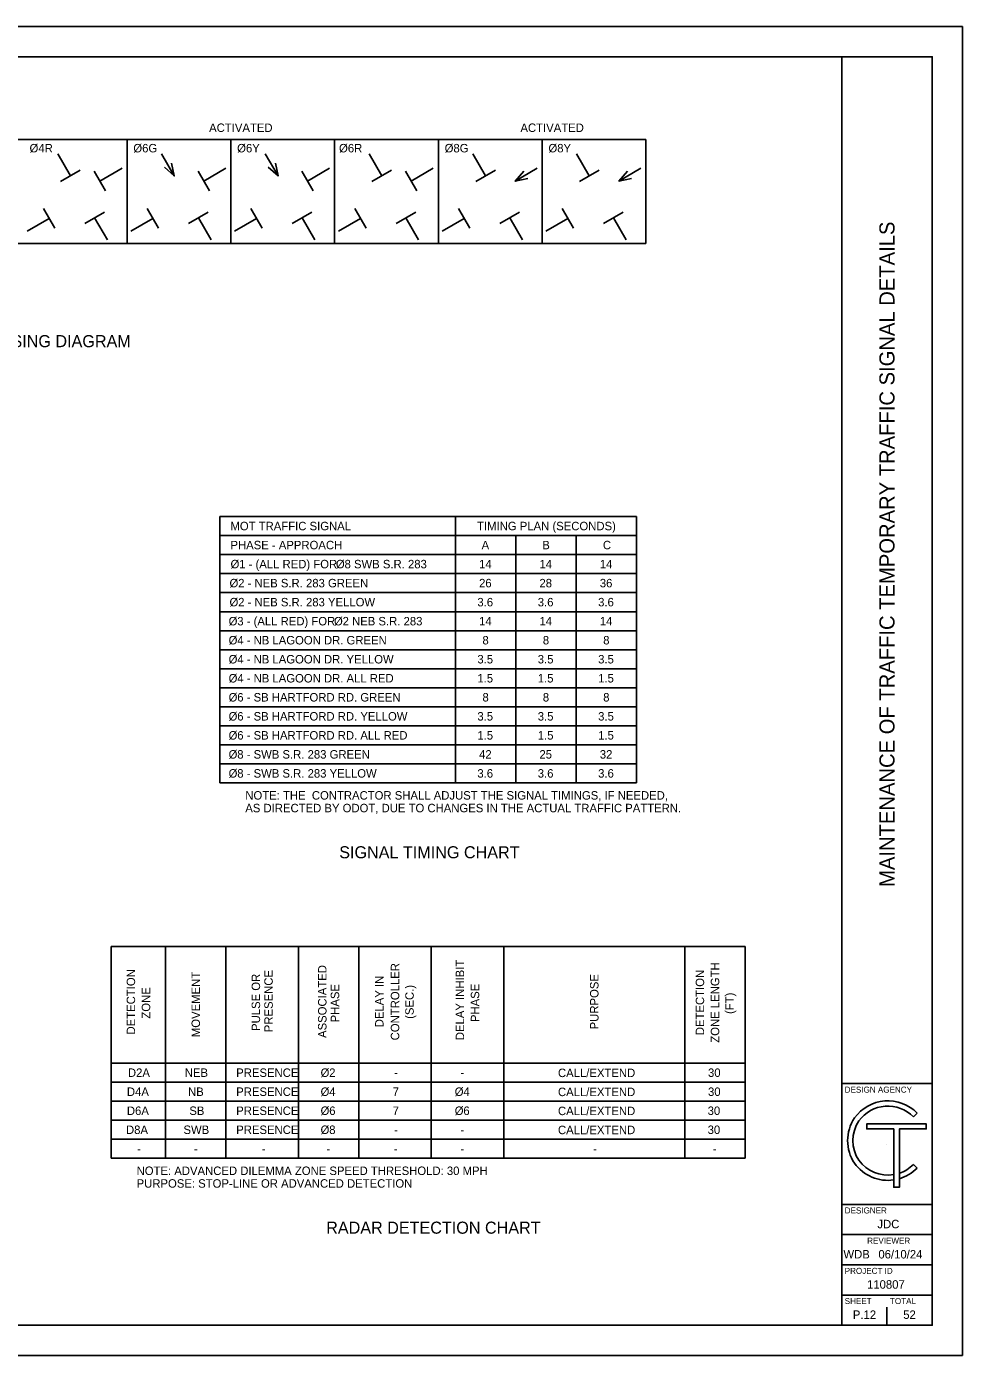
# Model space of a CAD drawing. Extents: x 0 to 34, y 0 to 22.
# Drawn here: x 18.5 to 34, y 0 to 22 of the extents above; entities that cross this region are included whole.
import ezdxf

# ---------------------------------------------------------------- set-up
doc = ezdxf.new("R2010")
doc.units = 0
for name, color, linetype in [('Default', 7, 'Continuous'), ('SG_P_Text', 7, 'Continuous'), ('SH_Border', 7, 'Continuous'), ('SH_Cut_Line', 7, 'Continuous'), ('SH_Data', 7, 'Continuous'), ('SH_Text', 7, 'Continuous'), ('ST_Details', 7, 'Continuous'), ('ST_Text', 7, 'Continuous')]:
    doc.layers.add(name, color=color, linetype=linetype)

msp = doc.modelspace()

# ---------------------------------------------------------------- linework, layer by layer
at = {"layer": 'Default'}
msp.add_line((22.402, 4.681), (22.402, 4.681), dxfattribs=at)
at = {"layer": 'SH_Border'}
for p, q in [((32, 0.5), (32, 21.5)), ((21.702, 9.478), (21.702, 13.888)), ((21.702, 13.888), (28.602, 13.888)), ((25.602, 9.478), (25.602, 13.888)), ((28.602, 9.478), (28.602, 13.888)), ((21.702, 13.573), (28.602, 13.573)), ((26.602, 9.478), (26.602, 13.573)), ((27.602, 9.478), (27.602, 13.573)), ((21.702, 13.258), (28.602, 13.258)), ((28.602, 12.943), (21.702, 12.943)), ((28.602, 12.628), (21.702, 12.628)), ((28.602, 12.313), (21.702, 12.313)), ((28.602, 11.998), (21.702, 11.998)), ((28.602, 11.683), (21.702, 11.683)), ((28.602, 11.368), (21.702, 11.368)), ((28.602, 11.053), (21.702, 11.053)), ((28.602, 10.738), (21.702, 10.738)), ((28.602, 10.423), (21.702, 10.423)), ((28.602, 10.108), (21.702, 10.108)), ((28.602, 9.793), (21.702, 9.793)), ((28.602, 9.478), (21.702, 9.478)), ((19.902, 3.263), (19.902, 6.77)), ((19.902, 6.77), (30.402, 6.77)), ((20.802, 3.263), (20.802, 6.77)), ((21.802, 3.263), (21.802, 6.77)), ((23.002, 3.263), (23.002, 6.77)), ((24.002, 3.263), (24.002, 6.77)), ((25.202, 6.77), (25.202, 3.263)), ((26.402, 6.77), (26.402, 3.263)), ((26.402, 6.77), (26.402, 3.263)), ((29.402, 6.77), (29.402, 3.263)), ((30.402, 6.77), (30.402, 3.263)), ((19.902, 4.838), (30.402, 4.838)), ((30.402, 4.523), (19.902, 4.523)), ((32, 4.5), (33.5, 4.5)), ((30.402, 4.208), (19.902, 4.208)), ((30.402, 3.893), (19.902, 3.893)), ((30.402, 3.578), (19.902, 3.578)), ((30.402, 3.263), (19.902, 3.263)), ((32, 2.5), (33.5, 2.5)), ((32, 2), (33.5, 2)), ((32, 1.5), (33.5, 1.5)), ((32, 1), (33.5, 1))]:
    msp.add_line(p, q, dxfattribs=at)
msp.add_lwpolyline([(1.5, 21.5), (33.5, 21.5), (33.5, 0.5), (1.5, 0.5)], close=True, dxfattribs=at)
at = {"layer": 'SH_Cut_Line'}
msp.add_lwpolyline([(0, 0), (34, 0), (34, 22), (0, 22)], close=True, dxfattribs=at)
at = {"layer": 'SH_Data'}
for p, q in [((32.75, 3.5), (32.75, 3.5)), ((32.375, 0.675), (32.375, 0.675)), ((32.75, 0.5), (32.75, 0.8))]:
    msp.add_line(p, q, dxfattribs=at)
at = {"layer": 'SH_Text'}
for p, q in [((33.249, 4.013), (33.187, 3.952)), ((33.249, 4.013), (33.187, 3.952)), ((33.402, 3.833), (32.414, 3.833)), ((32.414, 3.833), (32.414, 3.751)), ((32.414, 3.751), (32.863, 3.751)), ((32.863, 3.751), (32.863, 2.785)), ((32.956, 2.785), (32.956, 3.751)), ((32.956, 3.751), (33.402, 3.751)), ((33.402, 3.751), (33.402, 3.833)), ((33.187, 3.16), (33.249, 3.099)), ((33.187, 3.16), (33.249, 3.099)), ((32.863, 2.993), (32.863, 2.905)), ((32.863, 2.993), (32.863, 2.905)), ((32.956, 2.925), (32.956, 3.016)), ((32.956, 2.925), (32.956, 3.016)), ((32.863, 2.785), (32.956, 2.785))]:
    msp.add_line(p, q, dxfattribs=at)
for points in [[(20.902, 19.738), (20.945, 19.527), (20.784, 19.67)], [(22.62, 19.738), (22.664, 19.527), (22.502, 19.67)], [(26.801, 19.486), (26.59, 19.443), (26.733, 19.604)], [(28.52, 19.486), (28.309, 19.443), (28.452, 19.604)]]:
    msp.add_lwpolyline(points, dxfattribs=at)
msp.add_lwpolyline([(32.863, 3.751), (32.863, 2.785), (32.956, 2.785), (32.956, 3.751), (33.402, 3.751), (33.402, 3.833), (32.414, 3.833), (32.414, 3.751)], close=True, dxfattribs=at)
for centre, radius, start, end in [((32.766, 3.535), 0.68, 44.7027, 144.3276), ((32.766, 3.535), 0.68, 44.7027, 144.3276), ((32.766, 3.535), 0.593, 44.7362, 144.1102), ((32.766, 3.535), 0.593, 44.7362, 144.1102), ((32.764, 3.556), 0.666, 145.7329, 214.2671), ((32.764, 3.556), 0.666, 145.7329, 214.2671), ((32.764, 3.556), 0.579, 145.7266, 214.2734), ((32.764, 3.556), 0.579, 145.7266, 214.2734), ((32.766, 3.578), 0.68, 215.6724, 278.2613), ((32.766, 3.578), 0.68, 215.6724, 278.2613), ((32.766, 3.578), 0.593, 215.8898, 279.4882), ((32.766, 3.578), 0.593, 215.8898, 279.4882), ((32.766, 3.578), 0.593, 288.6992, 315.2638), ((32.766, 3.578), 0.593, 288.6992, 315.2638), ((32.766, 3.578), 0.68, 286.2291, 315.2973), ((32.766, 3.578), 0.68, 286.2291, 315.2973)]:
    msp.add_arc(centre, radius, start, end, dxfattribs=at)
at = {"layer": 'ST_Details'}
for p, q in [((4.697, 20.13), (28.758, 20.13)), ((20.165, 20.13), (20.165, 18.411)), ((21.883, 20.13), (21.883, 18.411)), ((23.602, 20.13), (23.602, 18.411)), ((25.321, 20.13), (25.321, 18.411)), ((27.039, 20.13), (27.039, 18.411)), ((28.758, 20.13), (28.758, 18.411)), ((19.226, 19.527), (19.016, 19.892)), ((20.945, 19.527), (20.734, 19.892)), ((22.664, 19.527), (22.453, 19.892)), ((24.382, 19.527), (24.172, 19.892)), ((26.101, 19.527), (25.89, 19.892)), ((27.82, 19.527), (27.609, 19.892)), ((19.063, 19.433), (19.389, 19.621)), ((19.621, 19.606), (19.809, 19.28)), ((19.715, 19.443), (20.08, 19.654)), ((21.34, 19.606), (21.528, 19.28)), ((21.434, 19.443), (21.799, 19.654)), ((23.059, 19.606), (23.247, 19.28)), ((23.153, 19.443), (23.518, 19.654)), ((24.219, 19.433), (24.545, 19.621)), ((24.777, 19.606), (24.965, 19.28)), ((24.871, 19.443), (25.236, 19.654)), ((25.938, 19.433), (26.264, 19.621)), ((26.59, 19.443), (26.955, 19.654)), ((27.657, 19.433), (27.983, 19.621)), ((28.309, 19.443), (28.674, 19.654)), ((18.967, 18.66), (18.779, 18.986)), ((19.789, 18.929), (19.463, 18.741)), ((20.686, 18.66), (20.498, 18.986)), ((21.508, 18.929), (21.182, 18.741)), ((22.404, 18.66), (22.216, 18.986)), ((23.226, 18.929), (22.901, 18.741)), ((24.123, 18.66), (23.935, 18.986)), ((24.945, 18.929), (24.619, 18.741)), ((25.842, 18.66), (25.654, 18.986)), ((26.664, 18.929), (26.338, 18.741)), ((27.56, 18.66), (27.372, 18.986)), ((28.383, 18.929), (28.057, 18.741)), ((18.873, 18.823), (18.508, 18.612)), ((19.626, 18.835), (19.837, 18.47)), ((20.592, 18.823), (20.227, 18.612)), ((21.345, 18.835), (21.556, 18.47)), ((22.31, 18.823), (21.945, 18.612)), ((23.063, 18.835), (23.274, 18.47)), ((24.029, 18.823), (23.664, 18.612)), ((24.782, 18.835), (24.993, 18.47)), ((25.748, 18.823), (25.383, 18.612)), ((26.501, 18.835), (26.712, 18.47)), ((27.466, 18.823), (27.101, 18.612)), ((28.22, 18.835), (28.43, 18.47)), ((4.697, 18.411), (28.758, 18.411))]:
    msp.add_line(p, q, dxfattribs=at)

# ---------------------------------------------------------------- texts
at = {"layer": 'SG_P_Text'}
for s, p in [('NOTE: THE  CONTRACTOR SHALL ADJUST THE SIGNAL TIMINGS, IF NEEDED, ', (22.122, 9.202)), ('AS DIRECTED BY ODOT, DUE TO CHANGES IN THE ACTUAL TRAFFIC PATTERN.', (22.122, 8.992)), ('NOTE: ADVANCED DILEMMA ZONE SPEED THRESHOLD: 30 MPH', (20.322, 2.987)), ('PURPOSE: STOP-LINE OR ADVANCED DETECTION', (20.322, 2.777))]:
    msp.add_text(s, height=0.14, rotation=0, dxfattribs=at).set_placement(p)
at = {"layer": 'SH_Data'}
msp.add_text('MAINTENANCE OF TRAFFIC TEMPORARY TRAFFIC SIGNAL DETAILS', height=0.25, rotation=90, dxfattribs=at).set_placement((32.875, 7.757))
for s, height, p in [('DESIGN AGENCY', 0.1, (32.05, 4.35)), ('DESIGNER', 0.1, (32.05, 2.35)), ('JDC', 0.14, (32.591, 2.105)), ('REVIEWER', 0.1, (32.422, 1.85)), ('WDB', 0.14, (32.029, 1.605)), ('06/10/24', 0.14, (32.608, 1.605)), ('PROJECT ID', 0.1, (32.05, 1.35)), ('110807', 0.14, (32.42, 1.105)), ('SHEET', 0.1, (32.05, 0.85)), ('TOTAL', 0.1, (32.8, 0.85)), ('P.12', 0.14, (32.185, 0.605)), ('52', 0.14, (33.019, 0.605))]:
    msp.add_text(s, height=height, dxfattribs=at).set_placement(p)
at = {"layer": 'SH_Text'}
for s, p in [('TEMPORARY TRAFFIC SIGNAL PHASING DIAGRAM', (13.672, 16.692)), ('SIGNAL TIMING CHART', (23.678, 8.23)), ('RADAR DETECTION CHART', (23.462, 2.015))]:
    msp.add_text(s, height=0.2, dxfattribs=at).set_placement(p)
for s, rotation, p in [('MOT TRAFFIC SIGNAL', 359.9999, (21.876, 13.661)), ('TIMING PLAN (SECONDS)', 359.9999, (25.961, 13.661)), ('PHASE - APPROACH', 359.9999, (21.876, 13.346)), ('A', 359.9999, (26.036, 13.346)), ('B', 359.9999, (27.041, 13.346)), ('C', 359.9999, (28.045, 13.346)), ('Ø', 359.9999, (21.878, 13.031)), ('1 - (ALL RED) FOR ', 359.9999, (22.021, 13.031)), ('Ø', 359.9999, (23.623, 13.031)), ('8 SWB S.R. 283', 359.9999, (23.766, 13.031)), ('14', 359.9999, (25.994, 13.031)), ('14', 359.9999, (26.994, 13.031)), ('14', 359.9999, (27.994, 13.031)), ('Ø', 359.9999, (21.861, 12.716)), ('2 - NEB S.R. 283 GREEN', 359.9999, (22.004, 12.716)), ('26', 359.9999, (25.994, 12.716)), ('28', 359.9999, (26.994, 12.716)), ('36', 359.9999, (27.994, 12.716)), ('Ø', 359.9999, (21.861, 12.401)), ('2 - NEB S.R. 283 YELLOW', 359.9999, (22.004, 12.401)), ('3.6', 359.9999, (25.966, 12.401)), ('3.6', 359.9999, (26.966, 12.401)), ('3.6', 359.9999, (27.966, 12.401)), ('Ø', 359.9999, (21.846, 12.086)), ('3 - (ALL RED) FOR ', 359.9999, (21.989, 12.086)), ('Ø', 359.9999, (23.591, 12.086)), ('2 NEB S.R. 283', 359.9999, (23.734, 12.086)), ('14', 359.9999, (25.994, 12.086)), ('14', 359.9999, (26.994, 12.086)), ('14', 359.9999, (27.994, 12.086)), ('Ø', 359.9999, (21.846, 11.771)), ('4 - NB LAGOON DR. GREEN', 359.9999, (21.989, 11.771)), ('8', 359.9999, (26.05, 11.771)), ('8', 359.9999, (27.05, 11.771)), ('8', 359.9999, (28.05, 11.771)), ('Ø', 359.9999, (21.846, 11.456)), ('4 - NB LAGOON DR. YELLOW', 359.9999, (21.989, 11.456)), ('3.5', 359.9999, (25.966, 11.456)), ('3.5', 359.9999, (26.966, 11.456)), ('3.5', 359.9999, (27.966, 11.456)), ('Ø', 359.9999, (21.846, 11.141)), ('4 - NB LAGOON DR. ALL RED', 359.9999, (21.989, 11.141)), ('1.5', 359.9999, (25.966, 11.141)), ('1.5', 359.9999, (26.966, 11.141)), ('1.5', 359.9999, (27.966, 11.141)), ('Ø', 359.9999, (21.846, 10.826)), ('6 - SB HARTFORD RD. GREEN', 359.9999, (21.989, 10.826)), ('8', 359.9999, (26.05, 10.826)), ('8', 359.9999, (27.05, 10.826)), ('8', 359.9999, (28.05, 10.826)), ('Ø', 359.9999, (21.846, 10.511)), ('6 - SB HARTFORD RD. YELLOW', 359.9999, (21.989, 10.511)), ('3.5', 359.9999, (25.966, 10.511)), ('3.5', 359.9999, (26.966, 10.511)), ('3.5', 359.9999, (27.966, 10.511)), ('Ø', 359.9999, (21.846, 10.196)), ('6 - SB HARTFORD RD. ALL RED', 359.9999, (21.989, 10.196)), ('1.5', 359.9999, (25.966, 10.196)), ('1.5', 359.9999, (26.966, 10.196)), ('1.5', 359.9999, (27.966, 10.196)), ('Ø', 359.9999, (21.846, 9.881)), ('8 - SWB S.R. 283 GREEN', 359.9999, (21.989, 9.881)), ('42', 359.9999, (25.994, 9.881)), ('25', 359.9999, (26.994, 9.881)), ('32', 359.9999, (27.994, 9.881)), ('Ø', 359.9999, (21.846, 9.566)), ('8 - SWB S.R. 283 YELLOW', 359.9999, (21.989, 9.566)), ('3.6', 359.9999, (25.966, 9.566)), ('3.6', 359.9999, (26.966, 9.566)), ('3.6', 359.9999, (27.966, 9.566)), ('ASSOCIATED', 89.9999, (23.467, 5.256)), ('CONTROLLER', 89.9999, (24.672, 5.216)), ('DELAY INHIBIT', 89.9999, (25.747, 5.219)), ('ZONE LENGTH', 89.9999, (29.972, 5.177)), ('DETECTION', 89.9999, (20.297, 5.313)), ('MOVEMENT', 89.9999, (21.372, 5.269)), ('PULSE OR', 89.9999, (22.367, 5.372)), ('PRESENCE', 89.9999, (22.577, 5.351)), ('DELAY IN', 89.9999, (24.412, 5.433)), ('PURPOSE', 89.9999, (27.972, 5.398)), ('DETECTION', 89.9999, (29.722, 5.302)), ('ZONE', 89.9999, (20.547, 5.576)), ('PHASE', 89.9999, (23.677, 5.514)), ('(SEC.)', 89.9999, (24.912, 5.572)), ('PHASE', 89.9999, (25.997, 5.519)), ('(FT)', 89.9999, (30.212, 5.653)), ('D2A', 359.9999, (20.178, 4.611)), ('NEB', 359.9999, (21.12, 4.611)), ('PRESENCE', 0, (21.972, 4.611)), ('Ø', 0, (23.369, 4.611)), ('2', 0, (23.512, 4.611)), ('-', 0, (24.585, 4.611)), ('-', 0, (25.685, 4.611)), ('CALL/EXTEND', 0, (27.301, 4.608)), ('30', 0, (29.786, 4.611)), ('D4A', 359.9999, (20.161, 4.296)), ('NB', 359.9999, (21.174, 4.296)), ('PRESENCE', 0, (21.972, 4.296)), ('Ø', 0, (23.369, 4.296)), ('4', 0, (23.512, 4.296)), ('7', 0, (24.563, 4.296)), ('Ø', 0, (25.591, 4.296)), ('4', 0, (25.734, 4.296)), ('CALL/EXTEND', 0, (27.301, 4.293)), ('30', 0, (29.786, 4.296)), ('D6A', 359.9999, (20.161, 3.981)), ('SB', 359.9999, (21.195, 3.981)), ('PRESENCE', 0, (21.972, 3.981)), ('Ø', 0, (23.369, 3.981)), ('6', 0, (23.512, 3.981)), ('7', 0, (24.563, 3.981)), ('Ø', 0, (25.591, 3.981)), ('6', 0, (25.734, 3.981)), ('CALL/EXTEND', 0, (27.301, 3.978)), ('30', 0, (29.78, 3.981)), ('D8A', 359.9999, (20.146, 3.666)), ('SWB', 359.9999, (21.098, 3.666)), ('PRESENCE', 0, (21.972, 3.666)), ('Ø', 0, (23.369, 3.666)), ('8', 0, (23.512, 3.666)), ('CALL/EXTEND', 0, (27.301, 3.663)), ('30', 0, (29.78, 3.666)), ('-', 0, (24.585, 3.666)), ('-', 0, (25.685, 3.666)), ('-', 359.9999, (20.33, 3.351)), ('-', 359.9999, (21.272, 3.351)), ('-', 0, (22.394, 3.351)), ('-', 0, (23.467, 3.351)), ('-', 0, (24.583, 3.351)), ('-', 0, (25.685, 3.351)), ('-', 0, (27.882, 3.348)), ('-', 0, (29.864, 3.351))]:
    msp.add_text(s, height=0.14, rotation=rotation, dxfattribs=at).set_placement(p)
at = {"layer": 'ST_Text'}
for s, p in [('ACTIVATED', (21.523, 20.255)), ('ACTIVATED', (26.679, 20.255)), ('Ø4R', (18.549, 19.917)), ('Ø6G', (20.268, 19.917)), ('Ø6Y', (21.987, 19.917)), ('Ø6R', (23.675, 19.917)), ('Ø8G', (25.424, 19.917)), ('Ø8Y', (27.143, 19.917))]:
    msp.add_text(s, height=0.14, dxfattribs=at).set_placement(p)

doc.saveas('drawing.dxf')
